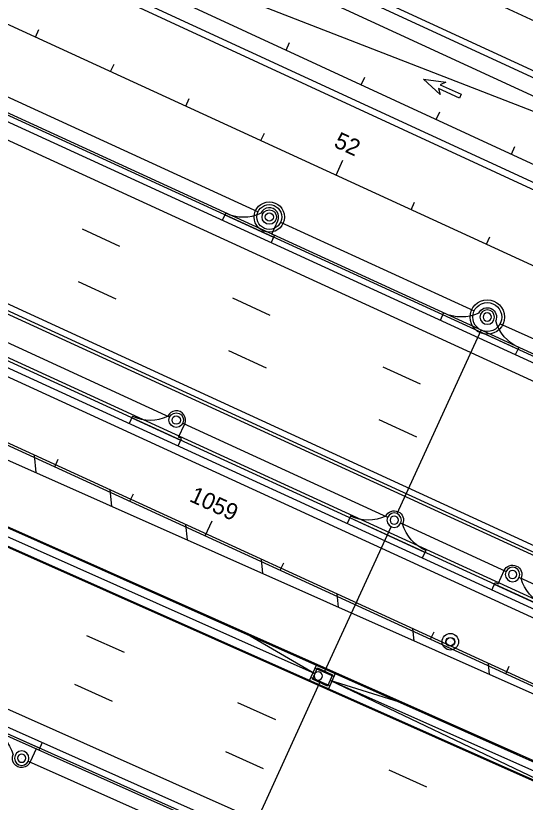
# Model space of a CAD drawing. Extents: x 468143 to 491361, y 1438528 to 1468730.
# Drawn here: x 488104.2 to 488227.5, y 1466882.5 to 1467072.5 of the extents above; entities that cross this region are included whole.
import ezdxf

# ---------------------------------------------------------------- set-up
doc = ezdxf.new("R2010")
doc.units = 0
doc.layers.add('Default', color=7, linetype='Continuous')
doc.layers.add('Xreference_dp', color=7, linetype='Continuous')

# ---------------------------------------------------------------- blocks, each defined once
blk = doc.blocks.new('POINT_DISPLAY')
at = {"layer": 'Default'}
blk.add_line((0, 0), (0, 0), dxfattribs=at)
blk = doc.blocks.new('InltCurb1_35')
at = {"layer": 'Default'}
for p, q in [((2.25, 2), (2.25, 5.5)), ((-10, 2), (-10, 0)), ((3, 2), (2.25, 2)), ((3, 0), (3, 2)), ((-10, 1.5), (3, 1.5))]:
    blk.add_line(p, q, dxfattribs=at)
for radius in [1.75, 1]:
    blk.add_circle((0, 5.5), radius, dxfattribs=at)
for centre, radius, start, end in [((0, 5.5), 2.25, 0, 180), ((-9.85, 12), 10, 269.1432, 319.4677)]:
    blk.add_arc(centre, radius, start, end, dxfattribs=at)
for p in [(0, 7.75), (-1.6, 6.2), (-1.22, 6.76), (-0.66, 7.12), (0, 7.25), (0, 7.25), (0.7, 7.1), (1.26, 6.72), (1.62, 6.16), (-1.75, 5.5), (-1.75, 5.5), (-1.62, 4.84), (-1.26, 4.28), (-0.7, 3.9), (0, 5.5), (0, 5.5), (0.66, 3.88), (1.22, 4.24), (1.6, 4.8), (1.75, 5.5), (1.75, 5.5), (0, 3.75), (0, 3.75), (0, 0), (0, 0)]:
    blk.add_blockref('POINT_DISPLAY', p, dxfattribs=at)
blk = doc.blocks.new('InltCurb2_35')
at = {"layer": 'Default'}
for p, q in [((-10, 2), (-10, 0)), ((10, 2), (10, 0)), ((-10, 1.5), (10, 1.5))]:
    blk.add_line(p, q, dxfattribs=at)
for radius in [1.75, 1]:
    blk.add_circle((0, 5.5), radius, dxfattribs=at)
for centre, radius, start, end in [((0, 5.5), 2.25, 0, 180), ((-9.85, 12), 10, 269.1432, 319.4677), ((9.85, 12), 10, 220.5323, 270.8568)]:
    blk.add_arc(centre, radius, start, end, dxfattribs=at)
for p in [(0, 7.75), (-1.6, 6.2), (-1.22, 6.76), (-0.66, 7.12), (0, 7.25), (0, 7.25), (0.7, 7.1), (1.26, 6.72), (1.62, 6.16), (-1.75, 5.5), (-1.75, 5.5), (-1.62, 4.84), (-1.26, 4.28), (-0.7, 3.9), (0, 5.5), (0, 5.5), (0.66, 3.88), (1.22, 4.24), (1.6, 4.8), (1.75, 5.5), (1.75, 5.5), (0, 3.75), (0, 3.75), (0, 0), (0, 0)]:
    blk.add_blockref('POINT_DISPLAY', p, dxfattribs=at)
blk = doc.blocks.new('InltCurb7_40')
at = {"layer": 'Default'}
for p, q in [((2.5, 4), (-2.5, 4)), ((-2.5, 4), (-2.5, 0)), ((2.5, 0), (2.5, 4)), ((2.5, 3.25), (-2.5, 3.25)), ((-2.5, 0.75), (2.5, 0.75)), ((-2.5, 0), (2.5, 0))]:
    blk.add_line(p, q, dxfattribs=at)
blk.add_lwpolyline([(-2, 0.5), (2, 0.5), (2, 3.5), (-2, 3.5)], close=True, dxfattribs=at)
blk.add_circle((-1.04, 2.19), 1, dxfattribs=at)
for p in [(0, 4), (-2, 3.5), (-2, 2), (-2, 2), (0, 3.5), (0, 3.5), (0, 2), (0, 2), (2, 3.5), (2, 2), (2, 2), (-2, 0.5), (0, 0.5), (0, 0.5), (0, 0), (0, 0), (2, 0.5)]:
    blk.add_blockref('POINT_DISPLAY', p, dxfattribs=at)
blk = doc.blocks.new('MHCover2')
at = {"layer": 'Default'}
for radius in [2, 1.06, 1]:
    blk.add_circle((0, 0), radius, dxfattribs=at)
for p in [(0, 2.5), (0, 2), (0, 2), (-2, 0), (-2, 0), (-1.83, 0.81), (-1.39, 1.43), (-0.75, 1.85), (0, 0), (0, 0), (0, 0), (0.81, 1.83), (1.43, 1.39), (1.85, 0.75), (2, 0), (2, 0), (-1.85, -0.75), (-1.43, -1.39), (-0.81, -1.83), (0.75, -1.85), (1.39, -1.43), (1.83, -0.81), (0, -2), (0, -2), (0, -2.5)]:
    blk.add_blockref('POINT_DISPLAY', p, dxfattribs=at)
blk = doc.blocks.new('JBottom60Dia')
at = {"layer": 'Default'}
for radius in [3.67, 3, 3]:
    blk.add_circle((0, 0), radius, dxfattribs=at)
for p in [(-2.09, 2.15), (-1.13, 2.78), (0, 3), (0, 3), (0, 3), (1.21, 2.75), (2.15, 2.09), (-2.75, 1.21), (0, 0), (0, 0), (0, 0), (2.78, 1.13), (3, 0), (3, 0), (-3, 0), (-3, 0), (-2.78, -1.13), (2.75, -1.21), (-2.15, -2.09), (-1.21, -2.75), (0, -3), (0, -3), (0, -3), (1.13, -2.78), (2.09, -2.15)]:
    blk.add_blockref('POINT_DISPLAY', p, dxfattribs=at)
blk = doc.blocks.new('JBottom70Dia')
at = {"layer": 'Default'}
for radius in [4.17, 3.5, 3.5]:
    blk.add_circle((0, 0), radius, dxfattribs=at)
for p in [(-2.44, 2.51), (-1.32, 3.24), (0, 3.5), (0, 3.5), (0, 3.5), (1.41, 3.2), (2.51, 2.44), (-3.5, 0), (-3.5, 0), (-3.2, 1.41), (0, 0), (0, 0), (0, 0), (3.24, 1.32), (-3.24, -1.32), (3.2, -1.41), (3.5, 0), (3.5, 0), (-2.51, -2.44), (-1.41, -3.2), (0, -3.5), (0, -3.5), (0, -3.5), (1.32, -3.24), (2.44, -2.51)]:
    blk.add_blockref('POINT_DISPLAY', p, dxfattribs=at)
blk = doc.blocks.new('DAMerge_2')
at = {"layer": 'Default'}
blk.add_lwpolyline([(0.71, -4.09), (0, -3.39), (3.95, 0.56), (2.42, 0.68), (7.31, 3.21), (4.77, -1.68), (4.66, -0.15), (0.71, -4.09)], dxfattribs=at)
blk = doc.blocks.new('DAMerge_6')
at = {"layer": 'Default'}
blk.add_lwpolyline([(0.71, -4.09), (0, -3.39), (3.95, 0.56), (2.42, 0.68), (7.31, 3.21), (4.77, -1.68), (4.66, -0.15), (0.71, -4.09)], dxfattribs=at)

msp = doc.modelspace()

# ---------------------------------------------------------------- linework, layer by layer
at = {"layer": 'Xreference_dp'}
for p, q in [((487372.29, 1467405.61), (488386.67, 1466939.92)), ((487416.58, 1467283.18), (488348.99, 1466855.64)), ((488019.07, 1467150.3), (488543.93, 1466907.95)), ((488033.37, 1467149.8), (488546.25, 1466912.98)), ((488041.18, 1467144.49), (488545.6, 1466911.58)), ((488012.78, 1467136.68), (488537.64, 1466894.33)), ((488012.78, 1467136.68), (488537.64, 1466894.33)), ((488009.46, 1467132.11), (488535.31, 1466889.3)), ((488031.54, 1467123.61), (488535.96, 1466890.7)), ((488062.74, 1467114.16), (488271.98, 1467032.97)), ((488379.42, 1466921.99), (487968.21, 1467110.55)), ((488378.58, 1466920.18), (487967.36, 1467108.73)), ((488379.21, 1466921.54), (487968, 1467110.09)), ((488376.92, 1466916.54), (487965.68, 1467105.11)), ((488246.41, 1467063.54), (488166.31, 1467100.53)), ((488151.31, 1467095.34), (488242.06, 1467053.44)), ((488361.29, 1466882.45), (487949.89, 1467071.09)), ((488361.91, 1466883.82), (487950.52, 1467072.45)), ((488361.91, 1466883.82), (487950.52, 1467072.45)), ((488360.97, 1466881.77), (487949.57, 1467070.41)), ((488109.04, 1467067.38), (488109.87, 1467069.2)), ((488169.66, 1467064.24), (488170.5, 1467066.05)), ((488356.7, 1466872.45), (487945.26, 1467061.11)), ((488357.02, 1466873.14), (487945.57, 1467061.79)), ((488356.08, 1466871.09), (487944.63, 1467059.75)), ((488127.21, 1467059.03), (488128.05, 1467060.85)), ((488355.24, 1466869.27), (487943.78, 1467057.94)), ((488187.82, 1467055.85), (488188.66, 1467057.67)), ((488094.23, 1467056.61), (488162.86, 1467025.14)), ((488145.39, 1467050.69), (488146.22, 1467052.51)), ((488205.98, 1467047.47), (488206.82, 1467049.29)), ((488349.2, 1466856.09), (487937.68, 1467044.79)), ((488163.56, 1467042.35), (488164.4, 1467044.16)), ((488224.14, 1467039.09), (488224.98, 1467040.9)), ((487935.21, 1467039.47), (488330.03, 1466863.88)), ((488181.74, 1467034), (488183.41, 1467037.64)), ((488199.92, 1467025.66), (488200.75, 1467027.47)), ((487928.9, 1467025.88), (488383.77, 1466823.62)), ((487929.01, 1467026.11), (488391.4, 1466820.5)), ((487927.11, 1467022.02), (488244.22, 1466881.02)), ((487927.22, 1467022.25), (488369.43, 1466825.62)), ((488168.31, 1467022.64), (488215.12, 1467001.18)), ((488129.47, 1467016.8), (488120.38, 1467020.97)), ((488218.09, 1467017.31), (488218.93, 1467019.13)), ((488070.13, 1467008.26), (488141.49, 1466975.54)), ((488128.55, 1467004.02), (488119.46, 1467008.19)), ((488165.83, 1467000.13), (488156.74, 1467004.3)), ((488196.53, 1466952.22), (488216.85, 1466996.54)), ((488249.66, 1466985.34), (488221.39, 1466998.06)), ((488164.91, 1466987.35), (488155.82, 1466991.52)), ((487912.06, 1466989.59), (488219.83, 1466852.74)), ((488202.19, 1466983.46), (488193.1, 1466987.62)), ((487910.37, 1466985.96), (488420.21, 1466759.26)), ((487909.53, 1466984.15), (488419.4, 1466757.43)), ((487909.74, 1466984.6), (488419.6, 1466757.89)), ((488144.67, 1466974.08), (488194.21, 1466951.36)), ((488201.27, 1466970.68), (488192.18, 1466974.85)), ((488108.69, 1466966.37), (488109.14, 1466962.12)), ((488113.7, 1466963.53), (488114.53, 1466965.34)), ((488126.99, 1466957.98), (488127.41, 1466953.99)), ((488131.88, 1466955.19), (488132.71, 1466957.01)), ((488145.3, 1466949.59), (488145.69, 1466945.86)), ((488150.06, 1466946.85), (488151.73, 1466950.49)), ((488179.05, 1466914.1), (488195.07, 1466949.04)), ((488222.84, 1466938.23), (488197.39, 1466949.9)), ((488098.03, 1466948.49), (488176.62, 1466913.54)), ((488163.6, 1466941.2), (488163.96, 1466937.74)), ((488168.24, 1466938.52), (488169.07, 1466940.34)), ((488125, 1466938.68), (488160.98, 1466922.68)), ((488303.29, 1466901.35), (488226.02, 1466936.77)), ((488181.9, 1466932.8), (488182.24, 1466929.61)), ((488186.42, 1466930.18), (488187.25, 1466932)), ((488200.2, 1466924.41), (488200.51, 1466921.48)), ((488121.38, 1466922.78), (488130.51, 1466918.72)), ((488160.98, 1466922.68), (488176.62, 1466913.54)), ((488204.6, 1466921.85), (488205.43, 1466923.66)), ((488218.51, 1466916.02), (488218.79, 1466913.35)), ((488222.78, 1466913.51), (488223.61, 1466915.33)), ((488118.44, 1466910.96), (488127.57, 1466906.89)), ((488159.39, 1466871.13), (488177.83, 1466911.36)), ((488322.78, 1466848.55), (488180.27, 1466911.92)), ((488197.08, 1466906.63), (488180.27, 1466911.92)), ((488247.88, 1466879.67), (488180.27, 1466911.92)), ((488157.93, 1466906.53), (488167.06, 1466902.47)), ((488197.08, 1466906.63), (488249.55, 1466883.3)), ((488154.99, 1466894.71), (488164.12, 1466890.64)), ((488107.28, 1466892.39), (488157.08, 1466870.25)), ((488194.47, 1466890.28), (488203.61, 1466886.22))]:
    msp.add_line(p, q, dxfattribs=at)

# ---------------------------------------------------------------- block references
for name, p, rotation in [('DAMerge_2', (488208.42, 1467051.45), 110.43256126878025), ('DAMerge_6', (488208.42, 1467051.45), 110.43256126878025), ('InltCurb1_35', (488163.29, 1467018.89), -24.63288075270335), ('JBottom60Dia', (488165.58, 1467023.89), 151.12101652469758), ('JBottom70Dia', (488218.31, 1466999.72), 69.27994773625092), ('InltCurb1_35', (488140.78, 1466969.81), -24.63288075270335), ('MHCover2', (488209.38, 1466921.25), 65.36711924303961)]:
    msp.add_blockref(name, p, dxfattribs=dict(at, rotation=rotation))
for name, p, yscale, rotation in [('InltCurb2_35', (488216.01, 1466994.72), -1.0000000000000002, 155.36711924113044), ('InltCurb2_35', (488193.51, 1466945.63), -1.0000000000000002, 155.36711924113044), ('InltCurb1_35', (488222.14, 1466932.5), -1, 155.36711924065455), ('InltCurb7_40', (488179.26, 1466914.56), -0.9999999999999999, -23.972703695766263), ('InltCurb1_35', (488107.92, 1466898.13), -1.0000000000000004, -23.972703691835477)]:
    msp.add_blockref(name, p, dxfattribs=dict(at, yscale=yscale, rotation=rotation))

# ---------------------------------------------------------------- texts
for s, rotation, p in [('52', 335.3408, (488180.98, 1467040.95)), ('1059', 335.3671, (488146.03, 1466955.3))]:
    msp.add_text(s, height=4, rotation=rotation, dxfattribs=at).set_placement(p)

doc.saveas('drawing.dxf')
